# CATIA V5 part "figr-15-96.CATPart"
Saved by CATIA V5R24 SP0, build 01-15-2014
Part number: Part1
Bounding box of the stored display mesh (mm): x -31.325 to 48, y -66.072 to 47.73, z 0 to 2
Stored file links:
  D:\KAVITA\CATIA V5-6R2014 Project_ Kavita\CATIA V5-6R2014_partfiles\Partfiles\c15_catia_v5-6r2014_prt\figr-15-96.CATPart
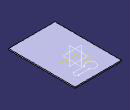
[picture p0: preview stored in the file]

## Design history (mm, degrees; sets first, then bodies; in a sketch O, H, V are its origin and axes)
SheetMetalParameters1: Thickness 2, BendRadius 4, KFactor 0.400515 {= log(min(100,max(20*SheetMetalParameters1.BendRadius,SheetMetalParameters1.Thickness)/SheetMetalParameters1.Thickness))/log(100)/2}, ReliefRadialLength 1, ReliefAxialLength 2, MinimumBendRadius 0
Body1 (main body)
  Sketch1 on xy-plane, origin (0, 0, 0), H (1, 0, 0), V (0, 1, 0)
    line L1 (-31.3255, 47.7299) -> (48, 47.7299)
    line L2 (48, 47.7299) -> (48, -66.0715)
    line L3 (48, -66.0715) -> (-31.3255, -66.0715)
    line L4 (-31.3255, -66.0715) -> (-31.3255, 47.7299)
    horizontal: L1 H, L3 H
    vertical: L2 V, L4 V
  Wall1: Thickness 2, Profile Sketch1, OffsetValue 0
  Sketch2 on face of Wall1, origin (0, 0, 2), H (1, 0, 0), V (0, 1, 0)
    construction line L1 (2.2258, 29) -> (27.2258, 29)
    point P1 (2.2258, 29)
    point P2 (27.2258, 29)
    line L2 (27.2258, 25) -> (9.154, 25)
    line L3 (9.154, 33) -> (27.2258, 33)
    arc A1 centre (2.2258, 29) radius 8 from (9.154, 25) to (9.154, 33) cw
    arc A2 centre (27.2258, 29) radius 4 from (27.2258, 33) to (27.2258, 25) cw
    radius A1 = 8
    radius A2 = 4
    distance P2 P1 = 25
    horizontal: L1 H
    tangency: A2 L2, A2 L3
    parallelism: L2 L3, L2 L1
